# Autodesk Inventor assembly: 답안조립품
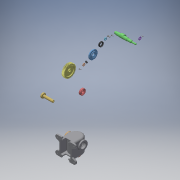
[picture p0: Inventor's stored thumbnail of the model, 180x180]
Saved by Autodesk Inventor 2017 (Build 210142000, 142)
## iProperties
Part Number: 답안조립품
Material: 일반
Document SubType Name: Assembly
Designer: user
Author: user
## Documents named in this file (17)
- C:\Users\user\Desktop\740904V1015\답안조립품.iam
- C:\Users\user\Desktop\740904V1015\본체.ipt
- C:\Users\user\Desktop\공용부품\공용부품_20240817_2\깊은 홈 볼베어링 6203.ipt
- C:\Users\user\Desktop\공용부품\공용부품_20240817_2\뒷커버.ipt
- C:\Users\user\Desktop\공용부품\공용부품_20240817_2\로드.ipt
- C:\Users\user\Desktop\공용부품\공용부품_20240817_2\부시.ipt
- C:\Users\user\Desktop\공용부품\공용부품_20240817_2\스퍼 기어.ipt
- C:\Users\user\Desktop\공용부품\공용부품_20240817_2\스프링와셔 M10.ipt
- C:\Users\user\Desktop\공용부품\공용부품_20240817_2\실링 패드.ipt
- C:\Users\user\Desktop\공용부품\공용부품_20240817_2\앞커버.ipt
- C:\Users\user\Desktop\공용부품\공용부품_20240817_2\오일실 17 32 8.ipt
- C:\Users\user\Desktop\공용부품\공용부품_20240817_2\육각 너트 M10x1.ipt
- C:\Users\user\Desktop\공용부품\공용부품_20240817_2\육각 머리 볼트 M6x0.75x12.ipt
- C:\Users\user\Desktop\공용부품\공용부품_20240817_2\육각 소켓 머리 볼트 M4x10.ipt
- C:\Users\user\Desktop\공용부품\공용부품_20240817_2\편심축.ipt
- C:\Users\user\Desktop\공용부품\공용부품_20240817_2\평와셔 M10.ipt
- C:\Users\user\Desktop\공용부품\공용부품_20240817_2\평행키 3x3x14.ipt
